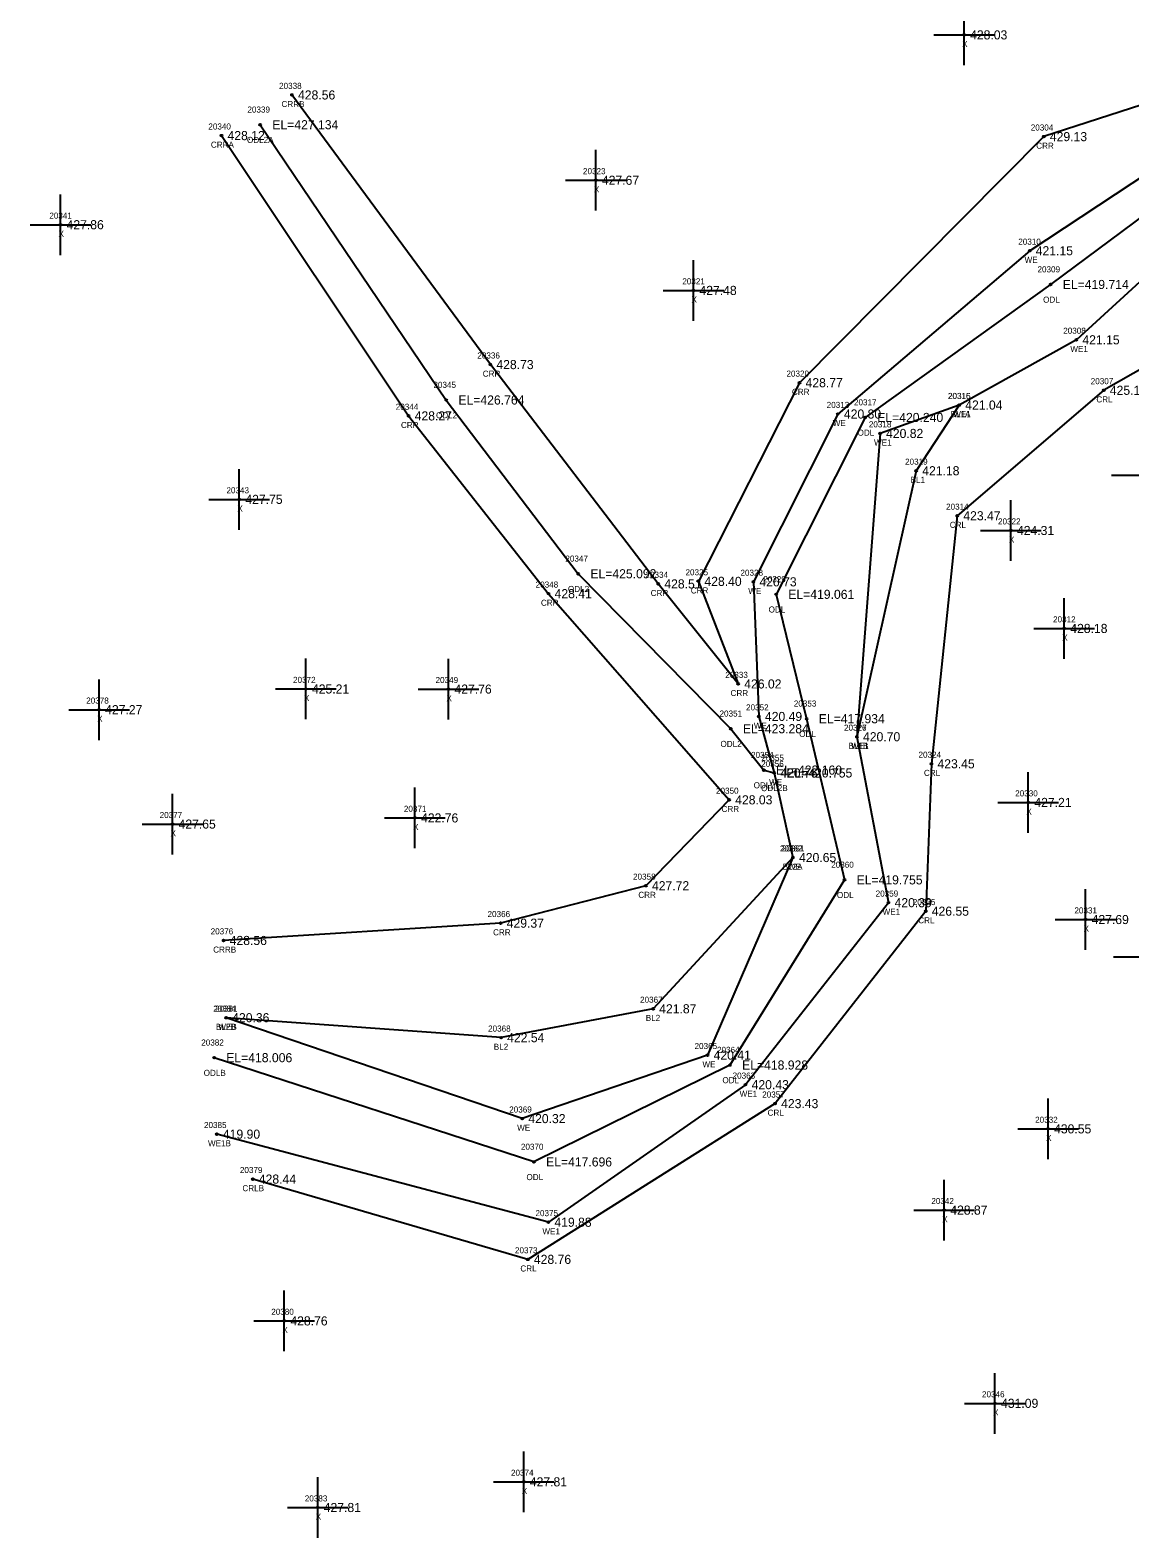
# Model space of a CAD drawing. Extents: x 1858461 to 1858936, y 1147060 to 1148183.
# Drawn here: x 1858460.6 to 1858641.9, y 1147371.4 to 1147619.9 of the extents above; entities that cross this region are included whole.
import ezdxf

# ---------------------------------------------------------------- set-up
doc = ezdxf.new("R2010")
doc.units = 0
for name, color, linetype in [('RD_DTM_BkLn1', 7, 'Continuous'), ('RD_DTM_BkLn_txCode', 7, 'Continuous'), ('RD_EX_H2O', 7, 'Continuous'), ('RD_EX_H2O_txCode', 7, 'Continuous'), ('RD_EX_Misc', 7, 'Continuous'), ('RD_EX_Misc_txCode', 7, 'Continuous'), ('RD_EX_TX_H2O_ELEV', 7, 'Continuous'), ('RD_EX_TX_Misc_ELEV', 7, 'Continuous'), ('RD_SMD_Locator', 7, 'Continuous')]:
    doc.layers.add(name, color=color, linetype=linetype)

msp = doc.modelspace()

# ---------------------------------------------------------------- linework, layer by layer
at = {"layer": 'RD_DTM_BkLn1'}
for points in [[(1858613.78, 1147558.13), (1858606.69, 1147547.3), (1858596.93, 1147503.46)], [(1858586.38, 1147483.55), (1858563.33, 1147458.62), (1858538.27, 1147453.86), (1858492.95, 1147457.15)]]:
    msp.add_lwpolyline(points, dxfattribs=at)
at = {"layer": 'RD_EX_H2O'}
for points in [[(1858879.83, 1148102.54), (1858871.42, 1148034.27), (1858866.93, 1147971.73), (1858863.21, 1147909.44), (1858860.9, 1147860.04), (1858873.82, 1147825.54), (1858891.79, 1147781.55), (1858894.95, 1147773.07), (1858887.01, 1147735.25), (1858825.08, 1147733.03), (1858791.14, 1147702.41), (1858765.02, 1147654.77), (1858740.99, 1147628.76), (1858706.35, 1147596.83), (1858671.87, 1147580.02), (1858637.61, 1147560.56), (1858613.46, 1147539.88), (1858609.2, 1147499), (1858608.26, 1147474.71), (1858583.43, 1147442.99), (1858542.68, 1147417.32), (1858497.34, 1147430.55)], [(1858719.03, 1147640.86), (1858697.04, 1147613.49), (1858661.98, 1147607.64), (1858625.4, 1147583.56), (1858593.78, 1147556.65), (1858579.85, 1147528.99), (1858580.76, 1147506.8), (1858583.29, 1147497.49), (1858586.38, 1147483.55), (1858572.3, 1147450.98), (1858541.76, 1147440.52), (1858492.95, 1147457.15)], [(1858724.58, 1147638.24), (1858698.73, 1147607.87), (1858662.17, 1147602.79), (1858628.85, 1147578), (1858598.27, 1147556.08), (1858583.61, 1147526.93), (1858588.64, 1147506.43), (1858594.87, 1147479.87), (1858576, 1147449.35), (1858543.69, 1147433.38), (1858490.97, 1147450.56)], [(1858731.96, 1147634.67), (1858700.72, 1147599.99), (1858663.73, 1147596.9), (1858633.09, 1147568.88), (1858613.78, 1147558.13), (1858600.73, 1147553.45), (1858596.93, 1147503.46), (1858602.13, 1147476.11), (1858578.57, 1147446.11), (1858546.06, 1147423.44), (1858491.42, 1147437.96)], [(1858681.73, 1147631.9), (1858663.61, 1147613.98), (1858627.73, 1147602.37), (1858587.46, 1147561.81), (1858570.79, 1147529.07), (1858577.35, 1147512.16), (1858564.18, 1147528.65), (1858536.5, 1147564.8), (1858503.8, 1147609.24)], [(1858492.18, 1147602.54), (1858523.03, 1147556.34), (1858546.09, 1147527.04), (1858575.86, 1147493.06), (1858562.14, 1147478.9), (1858538.2, 1147472.73), (1858492.54, 1147469.88)], [(1858498.57, 1147604.33), (1858529.24, 1147558.96), (1858550.99, 1147530.32), (1858576.12, 1147504.78), (1858581.59, 1147497.96), (1858583.29, 1147497.49)]]:
    msp.add_lwpolyline(points, dxfattribs=at)
at = {"layer": 'RD_EX_Misc'}
for p, q in [((1858614.58, 1147614.14), (1858614.58, 1147624.14)), ((1858609.58, 1147619.14), (1858619.58, 1147619.14)), ((1858553.89, 1147590.18), (1858553.89, 1147600.18)), ((1858548.89, 1147595.18), (1858558.89, 1147595.18)), ((1858465.65, 1147582.85), (1858465.65, 1147592.85)), ((1858460.65, 1147587.85), (1858470.65, 1147587.85)), ((1858569.97, 1147572.02), (1858569.97, 1147582.02)), ((1858564.97, 1147577.02), (1858574.97, 1147577.02)), ((1858495.12, 1147537.58), (1858495.12, 1147547.58)), ((1858638.89, 1147546.56), (1858648.89, 1147546.56)), ((1858490.12, 1147542.58), (1858500.12, 1147542.58)), ((1858622.3, 1147532.45), (1858622.3, 1147542.45)), ((1858617.3, 1147537.45), (1858627.3, 1147537.45)), ((1858631.09, 1147516.31), (1858631.09, 1147526.31)), ((1858626.09, 1147521.31), (1858636.09, 1147521.31)), ((1858506.1, 1147506.33), (1858506.1, 1147516.33)), ((1858529.59, 1147506.31), (1858529.59, 1147516.31)), ((1858472.01, 1147502.92), (1858472.01, 1147512.92)), ((1858501.1, 1147511.33), (1858511.1, 1147511.33)), ((1858524.59, 1147511.31), (1858534.59, 1147511.31)), ((1858467.01, 1147507.92), (1858477.01, 1147507.92)), ((1858625.17, 1147487.63), (1858625.17, 1147497.63)), ((1858484.11, 1147484.06), (1858484.11, 1147494.06)), ((1858524.08, 1147485.08), (1858524.08, 1147495.08)), ((1858620.17, 1147492.63), (1858630.17, 1147492.63)), ((1858479.11, 1147489.06), (1858489.11, 1147489.06)), ((1858519.08, 1147490.08), (1858529.08, 1147490.08)), ((1858634.61, 1147468.33), (1858634.61, 1147478.33)), ((1858629.61, 1147473.33), (1858639.61, 1147473.33)), ((1858639.24, 1147467.21), (1858649.24, 1147467.21)), ((1858628.42, 1147433.83), (1858628.42, 1147443.83)), ((1858623.42, 1147438.83), (1858633.42, 1147438.83)), ((1858611.31, 1147420.44), (1858611.31, 1147430.44)), ((1858606.31, 1147425.44), (1858616.31, 1147425.44)), ((1858502.54, 1147402.18), (1858502.54, 1147412.18)), ((1858497.54, 1147407.18), (1858507.54, 1147407.18)), ((1858619.68, 1147388.59), (1858619.68, 1147398.59)), ((1858614.68, 1147393.59), (1858624.68, 1147393.59)), ((1858542.01, 1147375.65), (1858542.01, 1147385.65)), ((1858508.04, 1147371.42), (1858508.04, 1147381.42)), ((1858537.01, 1147380.65), (1858547.01, 1147380.65)), ((1858503.04, 1147376.42), (1858513.04, 1147376.42))]:
    msp.add_line(p, q, dxfattribs=at)
at = {"layer": 'RD_SMD_Locator'}
for centre in [(1858614.58, 1147619.14), (1858503.8, 1147609.24), (1858492.18, 1147602.54), (1858498.57, 1147604.33), (1858627.73, 1147602.37), (1858553.89, 1147595.18), (1858465.65, 1147587.85), (1858625.4, 1147583.56), (1858628.85, 1147578), (1858569.97, 1147577.02), (1858633.09, 1147568.88), (1858536.5, 1147564.8), (1858587.46, 1147561.81), (1858637.61, 1147560.56), (1858529.24, 1147558.96), (1858613.78, 1147558.13), (1858613.78, 1147558.13), (1858523.03, 1147556.34), (1858593.78, 1147556.65), (1858598.27, 1147556.08), (1858600.73, 1147553.45), (1858606.69, 1147547.3), (1858495.12, 1147542.58), (1858613.46, 1147539.88), (1858622.3, 1147537.45), (1858550.99, 1147530.32), (1858564.18, 1147528.65), (1858570.79, 1147529.07), (1858579.85, 1147528.99), (1858546.09, 1147527.04), (1858583.61, 1147526.93), (1858631.09, 1147521.31), (1858506.1, 1147511.33), (1858529.59, 1147511.31), (1858577.35, 1147512.16), (1858472.01, 1147507.92), (1858580.76, 1147506.8), (1858588.64, 1147506.43), (1858576.12, 1147504.78), (1858596.93, 1147503.46), (1858596.93, 1147503.46), (1858581.59, 1147497.96), (1858609.2, 1147499), (1858583.29, 1147497.49), (1858583.29, 1147497.49), (1858575.86, 1147493.06), (1858625.17, 1147492.63), (1858484.11, 1147489.06), (1858524.08, 1147490.08), (1858586.38, 1147483.55), (1858586.38, 1147483.55), (1858562.14, 1147478.9), (1858594.87, 1147479.87), (1858602.13, 1147476.11), (1858538.2, 1147472.73), (1858608.26, 1147474.71), (1858634.61, 1147473.33), (1858492.54, 1147469.88), (1858563.33, 1147458.62), (1858492.95, 1147457.15), (1858492.95, 1147457.15), (1858538.27, 1147453.86), (1858490.97, 1147450.56), (1858572.3, 1147450.98), (1858576, 1147449.35), (1858578.57, 1147446.11), (1858583.43, 1147442.99), (1858541.76, 1147440.52), (1858491.42, 1147437.96), (1858628.42, 1147438.83), (1858543.69, 1147433.38), (1858497.34, 1147430.55), (1858546.06, 1147423.44), (1858611.31, 1147425.44), (1858542.68, 1147417.32), (1858502.54, 1147407.18), (1858619.68, 1147393.59), (1858542.01, 1147380.65), (1858508.04, 1147376.42)]:
    msp.add_circle(centre, 0.15, dxfattribs=at)

# ---------------------------------------------------------------- texts
at = {"layer": 'RD_DTM_BkLn_txCode'}
for s, p in [('20316', (1858611.92, 1147559.13)), ('BL1A', (1858612.37, 1147556.13)), ('20319', (1858604.86, 1147548.3)), ('BL1', (1858605.77, 1147545.3)), ('20327', (1858594.81, 1147504.46)), ('BL1B', (1858595.54, 1147501.46)), ('20362', (1858584.24, 1147484.55)), ('BL2A', (1858584.69, 1147481.55)), ('20367', (1858561.18, 1147459.62)), ('20384', (1858490.83, 1147458.15)), ('BL2B', (1858491.27, 1147455.15)), ('20368', (1858536.13, 1147454.86)), ('BL2', (1858562.12, 1147456.62)), ('BL2', (1858537.07, 1147451.86))]:
    msp.add_text(s, height=1, dxfattribs=at).set_placement(p)
at = {"layer": 'RD_EX_H2O_txCode'}
for s, p in [('20338', (1858501.68, 1147610.24)), ('20339', (1858496.46, 1147606.33)), ('CRRB', (1858502.08, 1147607.24)), ('20340', (1858490.02, 1147603.54)), ('ODL2A', (1858496.39, 1147601.33)), ('20304', (1858625.58, 1147603.37)), ('CRRA', (1858490.44, 1147600.54)), ('CRR', (1858626.48, 1147600.37)), ('20310', (1858623.52, 1147584.56)), ('WE', (1858624.56, 1147581.56)), ('20309', (1858626.69, 1147580)), ('ODL', (1858627.61, 1147575)), ('20308', (1858630.93, 1147569.88)), ('WE1', (1858632.1, 1147566.88)), ('20336', (1858534.36, 1147565.8)), ('CRR', (1858535.25, 1147562.8)), ('20320', (1858585.31, 1147562.81)), ('20307', (1858635.46, 1147561.56)), ('20345', (1858527.12, 1147560.96)), ('CRR', (1858586.21, 1147559.81)), ('20315', (1858611.95, 1147559.13)), ('20344', (1858520.91, 1147557.34)), ('20313', (1858591.94, 1147557.65)), ('20317', (1858596.44, 1147558.08)), ('CRL', (1858636.39, 1147558.56)), ('CRR', (1858521.77, 1147554.34)), ('ODL2', (1858527.55, 1147555.96)), ('WE', (1858592.94, 1147554.65)), ('20318', (1858598.89, 1147554.45)), ('WE1', (1858612.8, 1147556.13)), ('ODL', (1858597.03, 1147553.08)), ('WE1', (1858599.74, 1147551.45)), ('20314', (1858611.62, 1147540.88)), ('CRL', (1858612.23, 1147537.88)), ('20347', (1858548.87, 1147532.32)), ('20334', (1858562.07, 1147529.65)), ('20325', (1858568.67, 1147530.07)), ('20328', (1858577.73, 1147529.99)), ('20348', (1858543.97, 1147528.04)), ('ODL2', (1858549.29, 1147527.32)), ('CRR', (1858562.93, 1147526.65)), ('CRR', (1858569.54, 1147527.07)), ('WE', (1858579.01, 1147526.99)), ('20329', (1858581.49, 1147528.93)), ('CRR', (1858544.84, 1147525.04)), ('ODL', (1858582.37, 1147523.93)), ('20333', (1858575.23, 1147513.16)), ('CRR', (1858576.1, 1147510.16)), ('20351', (1858574.28, 1147506.78)), ('20352', (1858578.65, 1147507.8)), ('20353', (1858586.52, 1147508.43)), ('WE', (1858579.93, 1147504.8)), ('20326', (1858594.79, 1147504.46)), ('ODL2', (1858574.43, 1147501.78)), ('ODL', (1858587.4, 1147503.43)), ('20354', (1858579.47, 1147499.96)), ('20355', (1858581.17, 1147499.49)), ('WE1', (1858595.95, 1147501.46)), ('20324', (1858607.08, 1147500)), ('20356', (1858581.15, 1147498.49)), ('CRL', (1858607.97, 1147497)), ('ODL2', (1858579.9, 1147494.96)), ('ODL2B', (1858581.13, 1147494.49)), ('WE', (1858582.45, 1147495.49)), ('20350', (1858573.7, 1147494.06)), ('CRR', (1858574.61, 1147491.06)), ('20361', (1858584.53, 1147484.55)), ('20360', (1858592.69, 1147481.87)), ('20358', (1858560.02, 1147479.9)), ('WE', (1858585.55, 1147481.55)), ('CRR', (1858560.89, 1147476.9)), ('ODL', (1858593.63, 1147476.87)), ('20359', (1858600.01, 1147477.11)), ('20335', (1858606.14, 1147475.71)), ('20366', (1858536.04, 1147473.73)), ('WE1', (1858601.15, 1147474.11)), ('CRL', (1858607.03, 1147472.71)), ('20376', (1858490.4, 1147470.88)), ('CRR', (1858536.95, 1147470.73)), ('CRRB', (1858490.82, 1147467.88)), ('20381', (1858491.11, 1147458.15)), ('WEB', (1858491.66, 1147455.15)), ('20382', (1858488.85, 1147452.56)), ('20365', (1858570.16, 1147451.98)), ('20364', (1858573.86, 1147451.35)), ('ODLB', (1858489.25, 1147447.56)), ('WE', (1858571.46, 1147448.98)), ('20363', (1858576.43, 1147447.11)), ('ODL', (1858574.75, 1147446.35)), ('WE1', (1858577.59, 1147444.11)), ('20357', (1858581.31, 1147443.99)), ('20369', (1858539.61, 1147441.52)), ('CRL', (1858582.2, 1147440.99)), ('20385', (1858489.3, 1147438.96)), ('WE', (1858540.92, 1147438.52)), ('WE1B', (1858489.96, 1147435.96)), ('20370', (1858541.54, 1147435.38)), ('20379', (1858495.22, 1147431.55)), ('ODL', (1858542.45, 1147430.38)), ('CRLB', (1858495.64, 1147428.55)), ('20375', (1858543.94, 1147424.44)), ('WE1', (1858545.08, 1147421.44)), ('20373', (1858540.56, 1147418.32)), ('CRL', (1858541.45, 1147415.32))]:
    msp.add_text(s, height=1, dxfattribs=at).set_placement(p)
at = {"layer": 'RD_EX_Misc_txCode'}
for s, p in [('X', (1858614.27, 1147617.14)), ('20323', (1858551.77, 1147596.18)), ('X', (1858553.57, 1147593.18)), ('20341', (1858463.81, 1147588.85)), ('X', (1858465.33, 1147585.85)), ('20321', (1858568.14, 1147578.02)), ('X', (1858569.66, 1147575.02)), ('20343', (1858493, 1147543.58)), ('X', (1858494.8, 1147540.58)), ('20322', (1858620.18, 1147538.45)), ('X', (1858621.98, 1147535.45)), ('20312', (1858629.25, 1147522.31)), ('X', (1858630.77, 1147519.31)), ('20372', (1858503.98, 1147512.33)), ('20349', (1858527.47, 1147512.31)), ('X', (1858505.79, 1147509.33)), ('X', (1858529.27, 1147509.31)), ('20378', (1858469.89, 1147508.92)), ('X', (1858471.69, 1147505.92)), ('20330', (1858623.01, 1147493.63)), ('20377', (1858481.99, 1147490.06)), ('20371', (1858522.25, 1147491.08)), ('X', (1858624.85, 1147490.63)), ('X', (1858483.79, 1147487.06)), ('X', (1858523.77, 1147488.08)), ('20331', (1858632.77, 1147474.33)), ('X', (1858634.29, 1147471.33)), ('20332', (1858626.3, 1147439.83)), ('X', (1858628.1, 1147436.83)), ('20342', (1858609.19, 1147426.44)), ('X', (1858610.99, 1147423.44)), ('20380', (1858500.39, 1147408.18)), ('X', (1858502.23, 1147405.18)), ('20346', (1858617.54, 1147394.59)), ('X', (1858619.37, 1147391.59)), ('20374', (1858539.9, 1147381.65)), ('X', (1858541.7, 1147378.65)), ('20383', (1858505.92, 1147377.42)), ('X', (1858507.72, 1147374.42))]:
    msp.add_text(s, height=1, dxfattribs=at).set_placement(p)
at = {"layer": 'RD_EX_TX_H2O_ELEV'}
for s, p in [('428.56', (1858504.8, 1147608.49)), ('EL=427.134', (1858500.57, 1147603.58)), ('428.12', (1858493.18, 1147601.79)), ('429.13', (1858628.73, 1147601.62)), ('421.15', (1858626.4, 1147582.81)), ('EL=419.714', (1858630.85, 1147577.25)), ('421.15', (1858634.09, 1147568.13)), ('428.73', (1858537.5, 1147564.05)), ('428.77', (1858588.46, 1147561.06)), ('425.13', (1858638.61, 1147559.81)), ('EL=426.764', (1858531.24, 1147558.21)), ('420.80', (1858594.78, 1147555.9)), ('421.04', (1858614.78, 1147557.38)), ('428.27', (1858524.03, 1147555.59)), ('EL=420.240', (1858600.27, 1147555.33)), ('420.82', (1858601.73, 1147552.7)), ('423.47', (1858614.46, 1147539.13)), ('EL=425.092', (1858552.99, 1147529.57)), ('428.41', (1858547.09, 1147526.29)), ('428.51', (1858565.18, 1147527.9)), ('428.40', (1858571.79, 1147528.32)), ('420.73', (1858580.85, 1147528.24)), ('EL=419.061', (1858585.61, 1147526.18)), ('426.02', (1858578.35, 1147511.41)), ('EL=423.284', (1858578.12, 1147504.03)), ('420.49', (1858581.76, 1147506.05)), ('EL=417.934', (1858590.64, 1147505.68)), ('420.70', (1858597.93, 1147502.71)), ('EL=422.160', (1858583.59, 1147497.21)), ('420.76', (1858584.29, 1147496.74)), ('EL=420.755', (1858585.29, 1147496.74)), ('423.45', (1858610.2, 1147498.25)), ('428.03', (1858576.86, 1147492.31)), ('420.65', (1858587.38, 1147482.8)), ('EL=419.755', (1858596.87, 1147479.12)), ('427.72', (1858563.14, 1147478.15)), ('420.39', (1858603.13, 1147475.36)), ('426.55', (1858609.26, 1147473.96)), ('429.37', (1858539.2, 1147471.98)), ('428.56', (1858493.54, 1147469.13)), ('420.36', (1858493.95, 1147456.4)), ('EL=418.006', (1858492.97, 1147449.81)), ('420.41', (1858573.3, 1147450.23)), ('EL=418.928', (1858578, 1147448.6)), ('420.43', (1858579.57, 1147445.36)), ('423.43', (1858584.43, 1147442.24)), ('420.32', (1858542.76, 1147439.77)), ('419.90', (1858492.42, 1147437.21)), ('EL=417.696', (1858545.69, 1147432.63)), ('428.44', (1858498.34, 1147429.8)), ('419.88', (1858547.06, 1147422.69)), ('428.76', (1858543.68, 1147416.57))]:
    msp.add_text(s, height=1.5, dxfattribs=at).set_placement(p)
at = {"layer": 'RD_EX_TX_Misc_ELEV'}
for s, p in [('428.03', (1858615.58, 1147618.39)), ('427.67', (1858554.89, 1147594.43)), ('427.86', (1858466.65, 1147587.1)), ('427.48', (1858570.97, 1147576.27)), ('421.04', (1858614.78, 1147557.38)), ('421.18', (1858607.69, 1147546.55)), ('427.75', (1858496.12, 1147541.83)), ('424.31', (1858623.3, 1147536.7)), ('428.18', (1858632.09, 1147520.56)), ('425.21', (1858507.1, 1147510.58)), ('427.76', (1858530.59, 1147510.56)), ('427.27', (1858473.01, 1147507.17)), ('420.70', (1858597.93, 1147502.71)), ('427.21', (1858626.17, 1147491.88)), ('422.76', (1858525.08, 1147489.33)), ('427.65', (1858485.11, 1147488.31)), ('420.65', (1858587.38, 1147482.8)), ('427.69', (1858635.61, 1147472.58)), ('421.87', (1858564.33, 1147457.87)), ('420.36', (1858493.95, 1147456.4)), ('422.54', (1858539.27, 1147453.11)), ('430.55', (1858629.42, 1147438.08)), ('428.87', (1858612.31, 1147424.69)), ('428.76', (1858503.54, 1147406.43)), ('431.09', (1858620.68, 1147392.84)), ('427.81', (1858543.01, 1147379.9)), ('427.81', (1858509.04, 1147375.67))]:
    msp.add_text(s, height=1.5, dxfattribs=at).set_placement(p)

doc.saveas('drawing.dxf')
